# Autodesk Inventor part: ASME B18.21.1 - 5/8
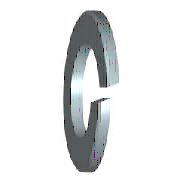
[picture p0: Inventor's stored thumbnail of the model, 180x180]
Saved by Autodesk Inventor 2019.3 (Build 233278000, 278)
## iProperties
Created: 2018-01
Part Number: ASME B18.21.1 - 5/8
Material: Steel, Mild
Description: Heavy Helical Spring Lock Washers(Inch Series)
Document SubType Name: Modeling
Standard: ASME B18.21.1
Designer: u1426
Standard Revision: 2009
Standards Organization: ANSI
Language: en-US
Size Designation: 5/8
Categories: <MemberInstance><Categories><Category DisplayName="Fasteners" InternalName="e4da775c-781d-43d5-af7c-5136215cf5a6" Mnemonic="FSTN"><Category DisplayName="Washers
Density: 7.85 g/cm^3
Appearance: Semi-Polished
IsCustomPart: 0
Author: u1426
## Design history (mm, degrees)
sketch "Sketch1"
  geometry: C1 r 13.805 at (0, 0); C2 r 7.976 at (0, 0); 1 further point
  constraints: 2 centre point, 2 coincident
  dimensions: "d0" = 15.9512 diameter of C2 (= SD1); "d1" = 27.6098 diameter of C1 (= SD2)
extrude "Body" new body sketch "Sketch1" distance "d2" = 4.8006 (= SD); taper "d3" = 0 deg
sketch "Sketch2"
  geometry: L1 (0, -7.976)-(0, 7.976) reference; L2 (4.801, 13.805)-(4.801, -13.805) reference; L3 (-1.2, 0)-(7.2, 0) reference; L4 (0, -0.96)-(4.801, -0.96); L5 (0, 0.96)-(4.801, 0.96)
  constraints: 4 end point, 4 point on line, 1 parallel
  dimensions: "d4" = 0.96012 distance from line of L3 L4.start (= 0.2 x SD); "d5" = 0.96012 distance from line of L3 L5.start (= 0.2 x SD); "d6" = 90 deg angle of L2 L4 (= FAWI)
extrude "Cut" cut sketch "Sketch2" stored distance "d7" = 4.8006 (= SD); taper "d8" = 0 deg
workaxis "Work Axis1"
workplane "Work Plane1"
body "Solid1"
other parameters: "SD1" = 15.9512 [user parameter; used in 1 equation term], "SD2" = 27.6098 [user parameter; used in 1 equation term], "SD" = 4.8006 [user parameter; used in 4 equation terms], "FAWI" = 90 deg [user parameter; used in 1 equation term], "d9" = 0, "d10" = 0, "d11" = 0, "d12" = 0, "NND" = 15.875 [user parameter]
